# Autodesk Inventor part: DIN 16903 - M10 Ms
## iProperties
Company: Mayer & Müller AG Schaltgeräte
Created: 2005-10
Part Number: DIN 16903 - M10 Ms
Material: Ms
Document SubType Name: Modeling
Designer: I.Baliuc
Manufacturer: Standard
Standards Organization: Custom
Description: Einpressmutter L
Density: 8.94 g/cm^3
Author: T.Messerschmitt
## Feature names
1. Drehung1 [Revolution]
2. Bohrung1 [Hole]
